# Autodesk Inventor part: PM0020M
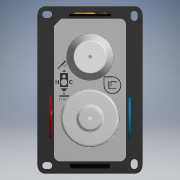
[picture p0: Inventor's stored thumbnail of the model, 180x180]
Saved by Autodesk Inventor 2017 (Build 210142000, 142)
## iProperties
Created: 2021-07
Part Number: PM0020M
Material: Generico
Document SubType Name: Modeling
Designer: CIANI
Density: 1 g/cm^3
Appearance: Default
Author: CIANI
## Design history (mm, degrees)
feature "Base2"
node "Solido1"
node "Solido3"
